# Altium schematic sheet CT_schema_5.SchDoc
size 298 x 271 mm
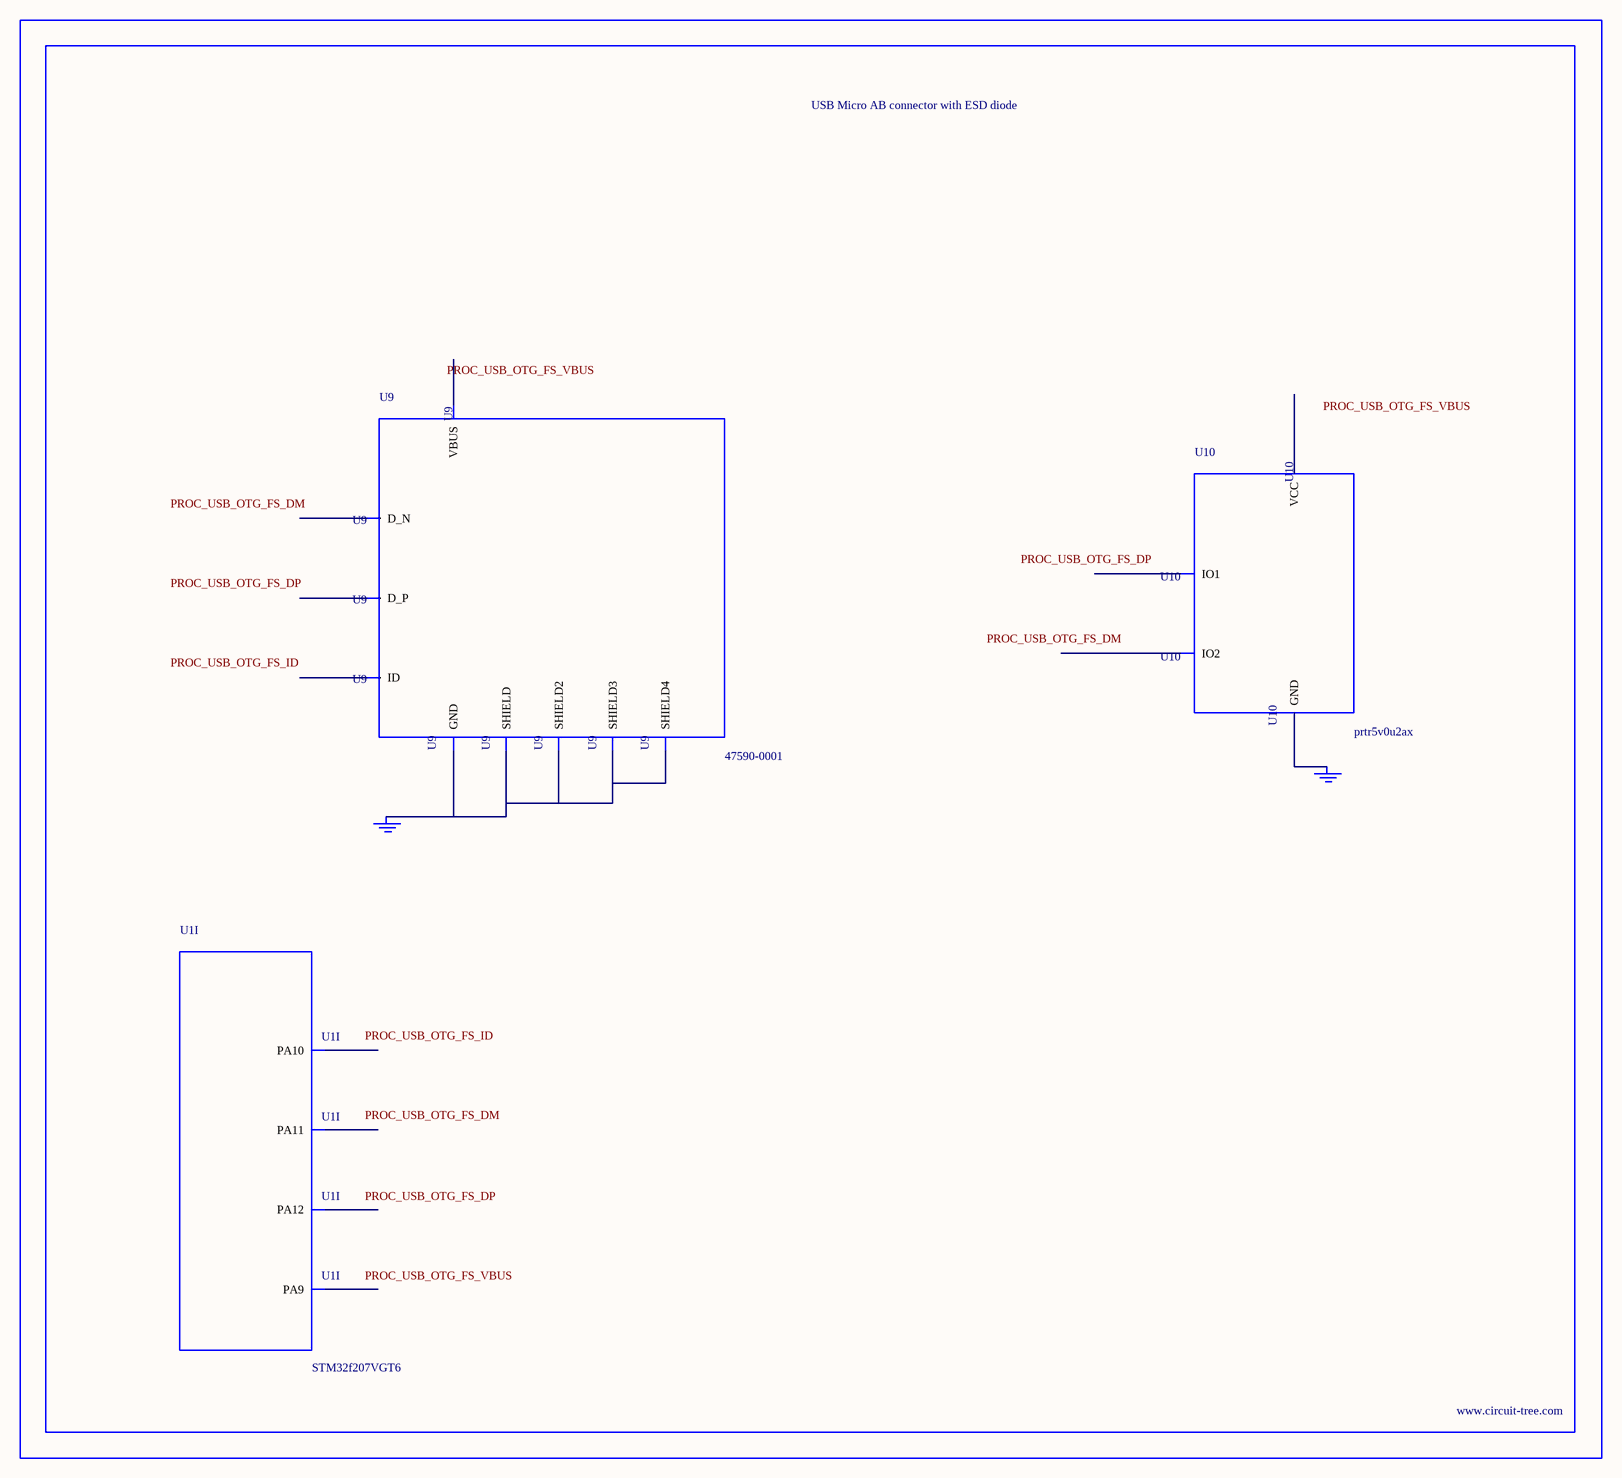
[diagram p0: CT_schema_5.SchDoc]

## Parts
BORDER4  (no value)
GND_INSTANCE_4_0  (no value)
GND_INSTANCE_4_1  (no value)
U1  STM32f207VGT6  [LQFP100]  (part I of 10)
U9  47590-0001  [MICRO_USB_AB]
U10  prtr5v0u2ax  [SOT143B]

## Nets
NetGND_INSTANCE_4_0_0: GND_INSTANCE_4_0.0(GND) U9.5(GND) U9.6(SHIELD) U9.7(SHIELD2) U9.8(SHIELD3) U9.9(SHIELD4)
NetGND_INSTANCE_4_1_0: GND_INSTANCE_4_1.0(GND) U10.1(GND)

Not connected (* = marked no-connect by the designer): U1 68(PA9) 69(PA10) 70(PA11) 71(PA12); U9 1(VBUS) 2(D_N) 3(D_P) 4(ID); U10 2(IO1) 3(IO2) 4(VCC)

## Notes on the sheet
- Labels drawn without touching a wire or pin: PROC_USB_OTG_FS_DM, PROC_USB_OTG_FS_DP, PROC_USB_OTG_FS_ID, PROC_USB_OTG_FS_VBUS

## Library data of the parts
BORDER4 = BORDER_PAGE4
GND_INSTANCE_4_0 GND_INSTANCE_4_1 = GND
